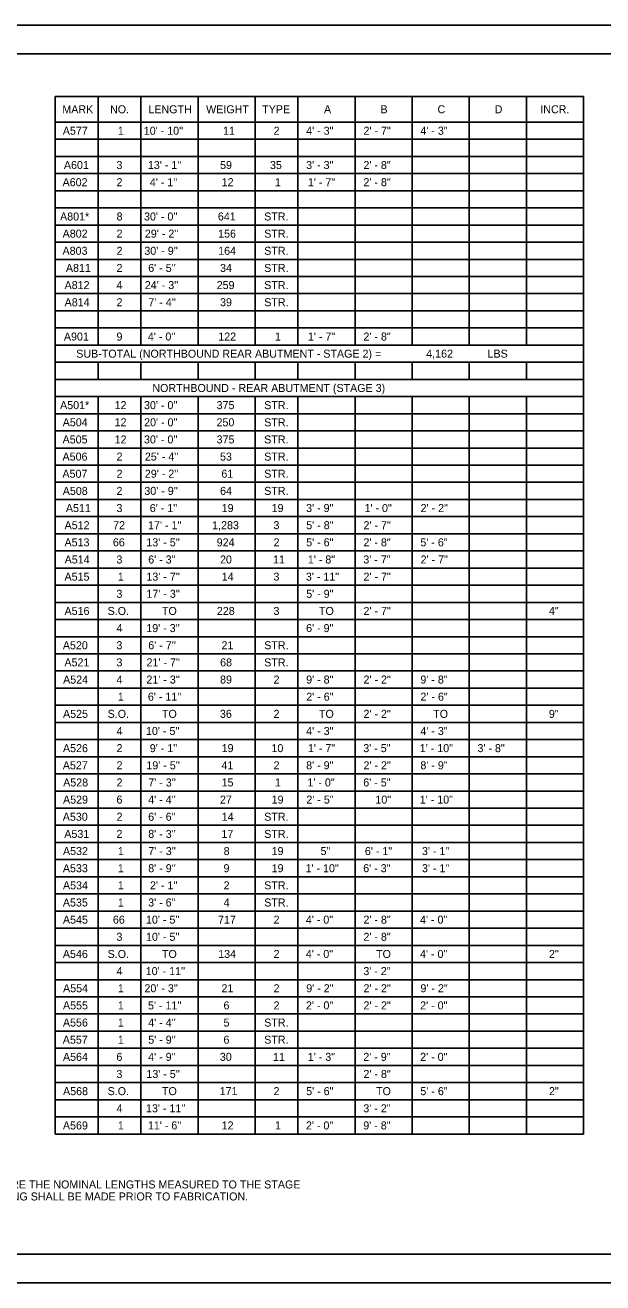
# Model space of a CAD drawing. Extents: x 1485751 to 1485785, y 230696.6 to 230718.6.
# Drawn here: x 1485763.13 to 1485773.25, y 230696.64 to 230718.64 of the extents above; entities that cross this region are included whole.
import ezdxf

# ---------------------------------------------------------------- set-up
doc = ezdxf.new("R2010")
doc.units = 0
for name, color, linetype in [('SH_Border', 7, 'Continuous'), ('SH_Cut_Line', 7, 'Continuous'), ('TX_P_Misc', 7, 'Continuous')]:
    doc.layers.add(name, color=color, linetype=linetype)

msp = doc.modelspace()

# ---------------------------------------------------------------- linework, layer by layer
at = {"layer": 'SH_Border'}
msp.add_lwpolyline([(1485753.033, 230718.141), (1485784.533, 230718.141), (1485784.533, 230697.141), (1485753.033, 230697.141)], close=True, dxfattribs=at)
at = {"layer": 'SH_Cut_Line'}
msp.add_lwpolyline([(1485751.033, 230718.641), (1485785.033, 230718.641), (1485785.033, 230696.641), (1485751.033, 230696.641)], close=True, dxfattribs=at)
at = {"layer": 'TX_P_Misc'}
for p, q in [((1485763.658, 230717.394), (1485772.908, 230717.394)), ((1485763.658, 230717.394), (1485763.658, 230699.244)), ((1485764.408, 230717.394), (1485764.408, 230713.044)), ((1485765.158, 230717.394), (1485765.158, 230713.044)), ((1485766.158, 230717.394), (1485766.158, 230713.044)), ((1485767.158, 230717.394), (1485767.158, 230713.044)), ((1485767.908, 230717.394), (1485767.908, 230713.044)), ((1485768.908, 230717.394), (1485768.908, 230713.044)), ((1485769.908, 230717.394), (1485769.908, 230713.044)), ((1485770.908, 230717.394), (1485770.908, 230713.044)), ((1485771.908, 230717.394), (1485771.908, 230713.044)), ((1485772.908, 230717.394), (1485772.908, 230699.244)), ((1485763.658, 230716.944), (1485772.908, 230716.944)), ((1485763.658, 230716.644), (1485772.908, 230716.644)), ((1485763.658, 230716.344), (1485772.908, 230716.344)), ((1485763.658, 230716.044), (1485772.908, 230716.044)), ((1485763.658, 230715.744), (1485772.908, 230715.744)), ((1485763.658, 230715.444), (1485772.908, 230715.444)), ((1485763.658, 230715.144), (1485772.908, 230715.144)), ((1485763.658, 230714.844), (1485772.908, 230714.844)), ((1485763.658, 230714.544), (1485772.908, 230714.544)), ((1485763.658, 230714.244), (1485772.908, 230714.244)), ((1485763.658, 230713.944), (1485772.908, 230713.944)), ((1485763.658, 230713.644), (1485772.908, 230713.644)), ((1485763.658, 230713.344), (1485772.908, 230713.344)), ((1485763.658, 230713.044), (1485772.908, 230713.044)), ((1485763.658, 230712.744), (1485772.908, 230712.744)), ((1485764.408, 230712.744), (1485764.408, 230712.444)), ((1485765.158, 230712.744), (1485765.158, 230712.444)), ((1485766.158, 230712.744), (1485766.158, 230712.444)), ((1485767.158, 230712.744), (1485767.158, 230712.444)), ((1485767.908, 230712.744), (1485767.908, 230712.444)), ((1485768.908, 230712.744), (1485768.908, 230712.444)), ((1485769.908, 230712.744), (1485769.908, 230712.444)), ((1485770.908, 230712.744), (1485770.908, 230712.444)), ((1485771.908, 230712.744), (1485771.908, 230712.444)), ((1485763.658, 230712.444), (1485772.908, 230712.444)), ((1485763.658, 230712.144), (1485772.908, 230712.144)), ((1485764.408, 230712.144), (1485764.408, 230699.244)), ((1485765.158, 230712.144), (1485765.158, 230699.244)), ((1485766.158, 230712.144), (1485766.158, 230699.244)), ((1485767.158, 230712.144), (1485767.158, 230699.244)), ((1485767.908, 230712.144), (1485767.908, 230699.244)), ((1485768.908, 230712.144), (1485768.908, 230699.244)), ((1485769.908, 230712.144), (1485769.908, 230699.244)), ((1485770.908, 230712.144), (1485770.908, 230699.244)), ((1485771.908, 230712.144), (1485771.908, 230699.244)), ((1485763.658, 230711.844), (1485772.908, 230711.844)), ((1485763.658, 230711.544), (1485772.908, 230711.544)), ((1485763.658, 230711.244), (1485772.908, 230711.244)), ((1485763.658, 230710.944), (1485772.908, 230710.944)), ((1485763.658, 230710.644), (1485772.908, 230710.644)), ((1485763.658, 230710.344), (1485772.908, 230710.344)), ((1485763.658, 230710.044), (1485772.908, 230710.044)), ((1485763.658, 230709.744), (1485772.908, 230709.744)), ((1485763.658, 230709.444), (1485772.908, 230709.444)), ((1485763.658, 230709.144), (1485772.908, 230709.144)), ((1485763.658, 230708.844), (1485772.908, 230708.844)), ((1485763.658, 230708.544), (1485772.908, 230708.544)), ((1485763.658, 230708.244), (1485772.908, 230708.244)), ((1485763.658, 230707.944), (1485772.908, 230707.944)), ((1485763.658, 230707.644), (1485772.908, 230707.644)), ((1485763.658, 230707.344), (1485772.908, 230707.344)), ((1485763.658, 230707.044), (1485772.908, 230707.044)), ((1485763.658, 230706.744), (1485772.908, 230706.744)), ((1485763.658, 230706.444), (1485772.908, 230706.444)), ((1485763.658, 230706.144), (1485772.908, 230706.144)), ((1485763.658, 230705.844), (1485772.908, 230705.844)), ((1485763.658, 230705.544), (1485772.908, 230705.544)), ((1485763.658, 230705.244), (1485772.908, 230705.244)), ((1485763.658, 230704.944), (1485772.908, 230704.944)), ((1485763.658, 230704.644), (1485772.908, 230704.644)), ((1485763.658, 230704.344), (1485772.908, 230704.344)), ((1485763.658, 230704.044), (1485772.908, 230704.044)), ((1485763.658, 230703.744), (1485772.908, 230703.744)), ((1485763.658, 230703.444), (1485772.908, 230703.444)), ((1485763.658, 230703.144), (1485772.908, 230703.144)), ((1485763.658, 230702.844), (1485772.908, 230702.844)), ((1485763.658, 230702.544), (1485772.908, 230702.544)), ((1485763.658, 230702.244), (1485772.908, 230702.244)), ((1485763.658, 230701.944), (1485772.908, 230701.944)), ((1485763.658, 230701.644), (1485772.908, 230701.644)), ((1485763.658, 230701.344), (1485772.908, 230701.344)), ((1485763.658, 230701.044), (1485772.908, 230701.044)), ((1485763.658, 230700.744), (1485772.908, 230700.744)), ((1485763.658, 230700.444), (1485772.908, 230700.444)), ((1485763.658, 230700.144), (1485772.908, 230700.144)), ((1485763.658, 230699.844), (1485772.908, 230699.844)), ((1485763.658, 230699.544), (1485772.908, 230699.544)), ((1485763.658, 230699.244), (1485772.908, 230699.244))]:
    msp.add_line(p, q, dxfattribs=at)

# ---------------------------------------------------------------- texts
for s, p in [('MARK', (1485763.782, 230717.099)), ('NO.', (1485764.618, 230717.099)), ('LENGTH', (1485765.288, 230717.099)), ('WEIGHT', (1485766.3, 230717.099)), ('TYPE', (1485767.282, 230717.099)), ('A', (1485768.364, 230717.099)), ('B', (1485769.353, 230717.099)), ('C', (1485770.352, 230717.099)), ('D', (1485771.353, 230717.099)), ('INCR.', (1485772.152, 230717.099)), ('A577', (1485763.79, 230716.724)), ('1', (1485764.754, 230716.724)), ("10' - 10''", (1485765.208, 230716.724)), ('11', (1485766.596, 230716.724)), ('2', (1485767.481, 230716.724)), ('4\' - 3"', (1485768.052, 230716.724)), ('2\' - 7"', (1485769.056, 230716.724)), ('4\' - 3"', (1485770.052, 230716.724)), ('A601', (1485763.809, 230716.124)), ('3', (1485764.729, 230716.124)), ("13' - 1''", (1485765.28, 230716.124)), ('59', (1485766.544, 230716.124)), ('35', (1485767.418, 230716.124)), ('3\' - 3"', (1485768.051, 230716.124)), ('2\' - 8"', (1485769.055, 230716.124)), ('A602', (1485763.786, 230715.824)), ('2', (1485764.731, 230715.824)), ("4' - 1''", (1485765.314, 230715.824)), ('12', (1485766.572, 230715.824)), ('1', (1485767.504, 230715.824)), ('1\' - 7"', (1485768.082, 230715.824)), ('2\' - 8"', (1485769.055, 230715.824)), ('A801*', (1485763.742, 230715.224)), ('8', (1485764.732, 230715.224)), ("30' - 0''", (1485765.212, 230715.224)), ('641', (1485766.506, 230715.224)), ('STR.', (1485767.317, 230715.224)), ('A802', (1485763.787, 230714.924)), ('2', (1485764.731, 230714.924)), ("29' - 2''", (1485765.227, 230714.924)), ('156', (1485766.51, 230714.924)), ('STR.', (1485767.317, 230714.924)), ('A803', (1485763.785, 230714.624)), ('2', (1485764.731, 230714.624)), ("30' - 9''", (1485765.218, 230714.624)), ('164', (1485766.511, 230714.624)), ('STR.', (1485767.317, 230714.624)), ('A811', (1485763.844, 230714.324)), ('2', (1485764.731, 230714.324)), ("6' - 5''", (1485765.286, 230714.324)), ('34', (1485766.544, 230714.324)), ('STR.', (1485767.317, 230714.324)), ('A812', (1485763.821, 230714.024)), ('4', (1485764.731, 230714.024)), ("24' - 3''", (1485765.226, 230714.024)), ('259', (1485766.485, 230714.024)), ('STR.', (1485767.317, 230714.024)), ('A814', (1485763.822, 230713.724)), ('2', (1485764.731, 230713.724)), ("7' - 4''", (1485765.288, 230713.724)), ('39', (1485766.543, 230713.724)), ('STR.', (1485767.317, 230713.724)), ('A901', (1485763.809, 230713.124)), ('9', (1485764.73, 230713.124)), ("4' - 0''", (1485765.28, 230713.124)), ('122', (1485766.513, 230713.124)), ('1', (1485767.504, 230713.124)), ('1\' - 7"', (1485768.082, 230713.124)), ('2\' - 8"', (1485769.055, 230713.124)), ('SUB-TOTAL (NORTHBOUND REAR ABUTMENT - STAGE 2) =', (1485764.025, 230712.824)), ('4,162', (1485770.154, 230712.824)), ('LBS', (1485771.228, 230712.824)), ('NORTHBOUND - REAR ABUTMENT (STAGE 3)', (1485765.358, 230712.224)), ('A501*', (1485763.742, 230711.924)), ('12', (1485764.697, 230711.924)), ("30' - 0''", (1485765.212, 230711.924)), ('375', (1485766.483, 230711.924)), ('STR.', (1485767.317, 230711.924)), ('A504', (1485763.788, 230711.624)), ('12', (1485764.697, 230711.624)), ("20' - 0''", (1485765.214, 230711.624)), ('250', (1485766.482, 230711.624)), ('STR.', (1485767.317, 230711.624)), ('A505', (1485763.786, 230711.324)), ('12', (1485764.697, 230711.324)), ("30' - 0''", (1485765.212, 230711.324)), ('375', (1485766.483, 230711.324)), ('STR.', (1485767.317, 230711.324)), ('A506', (1485763.785, 230711.024)), ('2', (1485764.731, 230711.024)), ("25' - 4''", (1485765.227, 230711.024)), ('53', (1485766.543, 230711.024)), ('STR.', (1485767.317, 230711.024)), ('A507', (1485763.783, 230710.724)), ('2', (1485764.731, 230710.724)), ("29' - 2''", (1485765.227, 230710.724)), ('61', (1485766.567, 230710.724)), ('STR.', (1485767.317, 230710.724)), ('A508', (1485763.789, 230710.424)), ('2', (1485764.731, 230710.424)), ("30' - 9''", (1485765.218, 230710.424)), ('64', (1485766.544, 230710.424)), ('STR.', (1485767.317, 230710.424)), ('A511', (1485763.844, 230710.124)), ('3', (1485764.729, 230710.124)), ("6' - 1''", (1485765.313, 230710.124)), ('19', (1485766.572, 230710.124)), ('19', (1485767.447, 230710.124)), ('3\' - 9"', (1485768.051, 230710.124)), ('1\' - 0"', (1485769.074, 230710.124)), ('2\' - 2"', (1485770.056, 230710.124)), ('A512', (1485763.821, 230709.824)), ('72', (1485764.671, 230709.824)), ("17' - 1''", (1485765.283, 230709.824)), ('1,283', (1485766.405, 230709.824)), ('3', (1485767.479, 230709.824)), ('5\' - 8"', (1485768.053, 230709.824)), ('2\' - 7"', (1485769.056, 230709.824)), ('A513', (1485763.82, 230709.524)), ('66', (1485764.667, 230709.524)), ("13' - 5''", (1485765.253, 230709.524)), ('924', (1485766.485, 230709.524)), ('2', (1485767.481, 230709.524)), ('5\' - 6"', (1485768.052, 230709.524)), ('2\' - 8"', (1485769.055, 230709.524)), ('5\' - 6"', (1485770.052, 230709.524)), ('A514', (1485763.822, 230709.224)), ('3', (1485764.729, 230709.224)), ("6' - 3''", (1485765.285, 230709.224)), ('20', (1485766.543, 230709.224)), ('11', (1485767.471, 230709.224)), ('1\' - 8"', (1485768.081, 230709.224)), ('3\' - 7"', (1485769.053, 230709.224)), ('2\' - 7"', (1485770.056, 230709.224)), ('A515', (1485763.82, 230708.924)), ('1', (1485764.754, 230708.924)), ("13' - 7''", (1485765.254, 230708.924)), ('14', (1485766.573, 230708.924)), ('3', (1485767.479, 230708.924)), ('3\' - 11"', (1485768.047, 230708.924)), ('2\' - 7"', (1485769.056, 230708.924)), ('3', (1485764.729, 230708.624)), ("17' - 3''", (1485765.254, 230708.624)), ('5\' - 9"', (1485768.052, 230708.624)), ('A516', (1485763.82, 230708.324)), ('S.O.', (1485764.575, 230708.324)), ('TO', (1485765.526, 230708.324)), ('228', (1485766.488, 230708.324)), ('3', (1485767.479, 230708.324)), ('TO', (1485768.276, 230708.324)), ('2\' - 7"', (1485769.056, 230708.324)), (' 4"', (1485772.251, 230708.324)), ('4', (1485764.731, 230708.024)), ("19' - 3''", (1485765.252, 230708.024)), ('6\' - 9"', (1485768.051, 230708.024)), ('A520', (1485763.791, 230707.724)), ('3', (1485764.729, 230707.724)), ("6' - 7''", (1485765.287, 230707.724)), ('21', (1485766.569, 230707.724)), ('STR.', (1485767.317, 230707.724)), ('A521', (1485763.818, 230707.424)), ('3', (1485764.729, 230707.424)), ("21' - 7''", (1485765.256, 230707.424)), ('68', (1485766.545, 230707.424)), ('STR.', (1485767.317, 230707.424)), ('A524', (1485763.795, 230707.124)), ('4', (1485764.731, 230707.124)), ("21' - 3''", (1485765.254, 230707.124)), ('89', (1485766.544, 230707.124)), ('2', (1485767.481, 230707.124)), ('9\' - 8"', (1485768.052, 230707.124)), ('2\' - 2"', (1485769.056, 230707.124)), ('9\' - 8"', (1485770.052, 230707.124)), ('1', (1485764.754, 230706.824)), ("6' - 11''", (1485765.28, 230706.824)), ('2\' - 6"', (1485768.053, 230706.824)), ('2\' - 6"', (1485770.053, 230706.824)), ('A525', (1485763.794, 230706.524)), ('S.O.', (1485764.575, 230706.524)), ('TO', (1485765.526, 230706.524)), ('36', (1485766.542, 230706.524)), ('2', (1485767.481, 230706.524)), ('TO', (1485768.276, 230706.524)), ('2\' - 2"', (1485769.056, 230706.524)), ('TO', (1485770.276, 230706.524)), (' 9"', (1485772.25, 230706.524)), ('4', (1485764.731, 230706.224)), ("10' - 5''", (1485765.247, 230706.224)), ('4\' - 3"', (1485768.052, 230706.224)), ('4\' - 3"', (1485770.052, 230706.224)), ('A526', (1485763.793, 230705.924)), ('2', (1485764.731, 230705.924)), ("9' - 1''", (1485765.313, 230705.924)), ('19', (1485766.572, 230705.924)), ('10', (1485767.444, 230705.924)), ('1\' - 7"', (1485768.082, 230705.924)), ('3\' - 5"', (1485769.052, 230705.924)), ('1\' - 10"', (1485770.041, 230705.924)), ('3\' - 8"', (1485771.052, 230705.924)), ('A527', (1485763.79, 230705.624)), ('2', (1485764.731, 230705.624)), ("19' - 5''", (1485765.253, 230705.624)), ('41', (1485766.568, 230705.624)), ('2', (1485767.481, 230705.624)), ('8\' - 9"', (1485768.052, 230705.624)), ('2\' - 2"', (1485769.056, 230705.624)), ('8\' - 9"', (1485770.052, 230705.624)), ('A528', (1485763.796, 230705.324)), ('2', (1485764.731, 230705.324)), ("7' - 3''", (1485765.287, 230705.324)), ('15', (1485766.571, 230705.324)), ('1', (1485767.504, 230705.324)), ('1\' - 0"', (1485768.074, 230705.324)), ('6\' - 5"', (1485769.052, 230705.324)), ('A529', (1485763.794, 230705.024)), ('6', (1485764.729, 230705.024)), ("4' - 4''", (1485765.286, 230705.024)), ('27', (1485766.542, 230705.024)), ('19', (1485767.447, 230705.024)), ('2\' - 5"', (1485768.055, 230705.024)), (' 10"', (1485769.212, 230705.024)), ('1\' - 10"', (1485770.041, 230705.024)), ('A530', (1485763.789, 230704.724)), ('2', (1485764.731, 230704.724)), ("6' - 6''", (1485765.285, 230704.724)), ('14', (1485766.573, 230704.724)), ('STR.', (1485767.317, 230704.724)), ('A531', (1485763.816, 230704.424)), ('2', (1485764.731, 230704.424)), ("8' - 3''", (1485765.286, 230704.424)), ('17', (1485766.568, 230704.424)), ('STR.', (1485767.317, 230704.424)), ('A532', (1485763.793, 230704.124)), ('1', (1485764.754, 230704.124)), ("7' - 3''", (1485765.287, 230704.124)), ('8', (1485766.607, 230704.124)), ('19', (1485767.447, 230704.124)), (' 5"', (1485768.251, 230704.124)), ('6\' - 1"', (1485769.08, 230704.124)), ('3\' - 1"', (1485770.08, 230704.124)), ('A533', (1485763.791, 230703.824)), ('1', (1485764.754, 230703.824)), ("8' - 9''", (1485765.286, 230703.824)), ('9', (1485766.605, 230703.824)), ('19', (1485767.447, 230703.824)), ('1\' - 10"', (1485768.041, 230703.824)), ('6\' - 3"', (1485769.051, 230703.824)), ('3\' - 1"', (1485770.08, 230703.824)), ('A534', (1485763.793, 230703.524)), ('1', (1485764.754, 230703.524)), ("2' - 1''", (1485765.316, 230703.524)), ('2', (1485766.606, 230703.524)), ('STR.', (1485767.317, 230703.524)), ('A535', (1485763.791, 230703.224)), ('1', (1485764.754, 230703.224)), ("3' - 6''", (1485765.285, 230703.224)), ('4', (1485766.606, 230703.224)), ('STR.', (1485767.317, 230703.224)), ('A545', (1485763.792, 230702.924)), ('66', (1485764.667, 230702.924)), ("10' - 5''", (1485765.247, 230702.924)), ('717', (1485766.509, 230702.924)), ('2', (1485767.481, 230702.924)), ('4\' - 0"', (1485768.046, 230702.924)), ('2\' - 8"', (1485769.055, 230702.924)), ('4\' - 0"', (1485770.046, 230702.924)), ('3', (1485764.729, 230702.624)), ("10' - 5''", (1485765.247, 230702.624)), ('2\' - 8"', (1485769.055, 230702.624)), ('A546', (1485763.791, 230702.324)), ('S.O.', (1485764.575, 230702.324)), ('TO', (1485765.526, 230702.324)), ('134', (1485766.511, 230702.324)), ('2', (1485767.481, 230702.324)), ('4\' - 0"', (1485768.046, 230702.324)), ('TO', (1485769.276, 230702.324)), ('4\' - 0"', (1485770.046, 230702.324)), (' 2"', (1485772.252, 230702.324)), ('4', (1485764.731, 230702.024)), ("10' - 11''", (1485765.242, 230702.024)), ('3\' - 2"', (1485769.053, 230702.024)), ('A554', (1485763.794, 230701.724)), ('1', (1485764.754, 230701.724)), ("20' - 3''", (1485765.22, 230701.724)), ('21', (1485766.569, 230701.724)), ('2', (1485767.481, 230701.724)), ('9\' - 2"', (1485768.053, 230701.724)), ('2\' - 2"', (1485769.056, 230701.724)), ('9\' - 2"', (1485770.053, 230701.724)), ('A555', (1485763.793, 230701.424)), ('1', (1485764.754, 230701.424)), ("5' - 11''", (1485765.282, 230701.424)), ('6', (1485766.604, 230701.424)), ('2', (1485767.481, 230701.424)), ('2\' - 0"', (1485768.048, 230701.424)), ('2\' - 2"', (1485769.056, 230701.424)), ('2\' - 0"', (1485770.048, 230701.424)), ('A556', (1485763.792, 230701.124)), ('1', (1485764.754, 230701.124)), ("4' - 4''", (1485765.286, 230701.124)), ('5', (1485766.604, 230701.124)), ('STR.', (1485767.317, 230701.124)), ('A557', (1485763.789, 230700.824)), ('1', (1485764.754, 230700.824)), ("5' - 9''", (1485765.286, 230700.824)), ('6', (1485766.604, 230700.824)), ('STR.', (1485767.317, 230700.824)), ('A564', (1485763.793, 230700.524)), ('6', (1485764.729, 230700.524)), ("4' - 9''", (1485765.285, 230700.524)), ('30', (1485766.54, 230700.524)), ('11', (1485767.471, 230700.524)), ('1\' - 3"', (1485768.08, 230700.524)), ('2\' - 9"', (1485769.053, 230700.524)), ('2\' - 0"', (1485770.048, 230700.524)), ('3', (1485764.729, 230700.224)), ("13' - 5''", (1485765.253, 230700.224)), ('2\' - 8"', (1485769.055, 230700.224)), ('A568', (1485763.794, 230699.924)), ('S.O.', (1485764.575, 230699.924)), ('TO', (1485765.526, 230699.924)), ('171', (1485766.536, 230699.924)), ('2', (1485767.481, 230699.924)), ('5\' - 6"', (1485768.052, 230699.924)), ('TO', (1485769.276, 230699.924)), ('5\' - 6"', (1485770.052, 230699.924)), (' 2"', (1485772.252, 230699.924)), ('4', (1485764.731, 230699.624)), ("13' - 11''", (1485765.247, 230699.624)), ('3\' - 2"', (1485769.053, 230699.624)), ('A569', (1485763.792, 230699.324)), ('1', (1485764.754, 230699.324)), ("11' - 6''", (1485765.28, 230699.324)), ('12', (1485766.572, 230699.324)), ('1', (1485767.504, 230699.324)), ('2\' - 0"', (1485768.048, 230699.324)), ('9\' - 8"', (1485769.052, 230699.324)), ('* - INDICATES BARS REQUIRING MECHANICAL CONNECTORS.  THE LENGTHS SHOWN IN THE TABLE ARE THE NOMINAL LENGTHS MEASURED TO THE STAGE', (1485753.586, 230698.292)), ('    CONSTRUCTION JOINT.  ADJUSTMENT IN THE LENGTHS OF THE BARS DUE TO MECHANICAL SPLICING SHALL BE MADE PRIOR TO FABRICATION.', (1485753.586, 230698.082))]:
    msp.add_text(s, height=0.14, dxfattribs=at).set_placement(p)

doc.saveas('drawing.dxf')
